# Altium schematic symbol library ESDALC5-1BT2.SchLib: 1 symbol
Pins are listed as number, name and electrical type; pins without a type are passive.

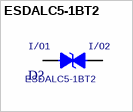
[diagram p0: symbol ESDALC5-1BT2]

## ESDALC5-1BT2
designator D?
footprint ST_SOD882TB
pins: 1 I/O1, 2 I/O2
